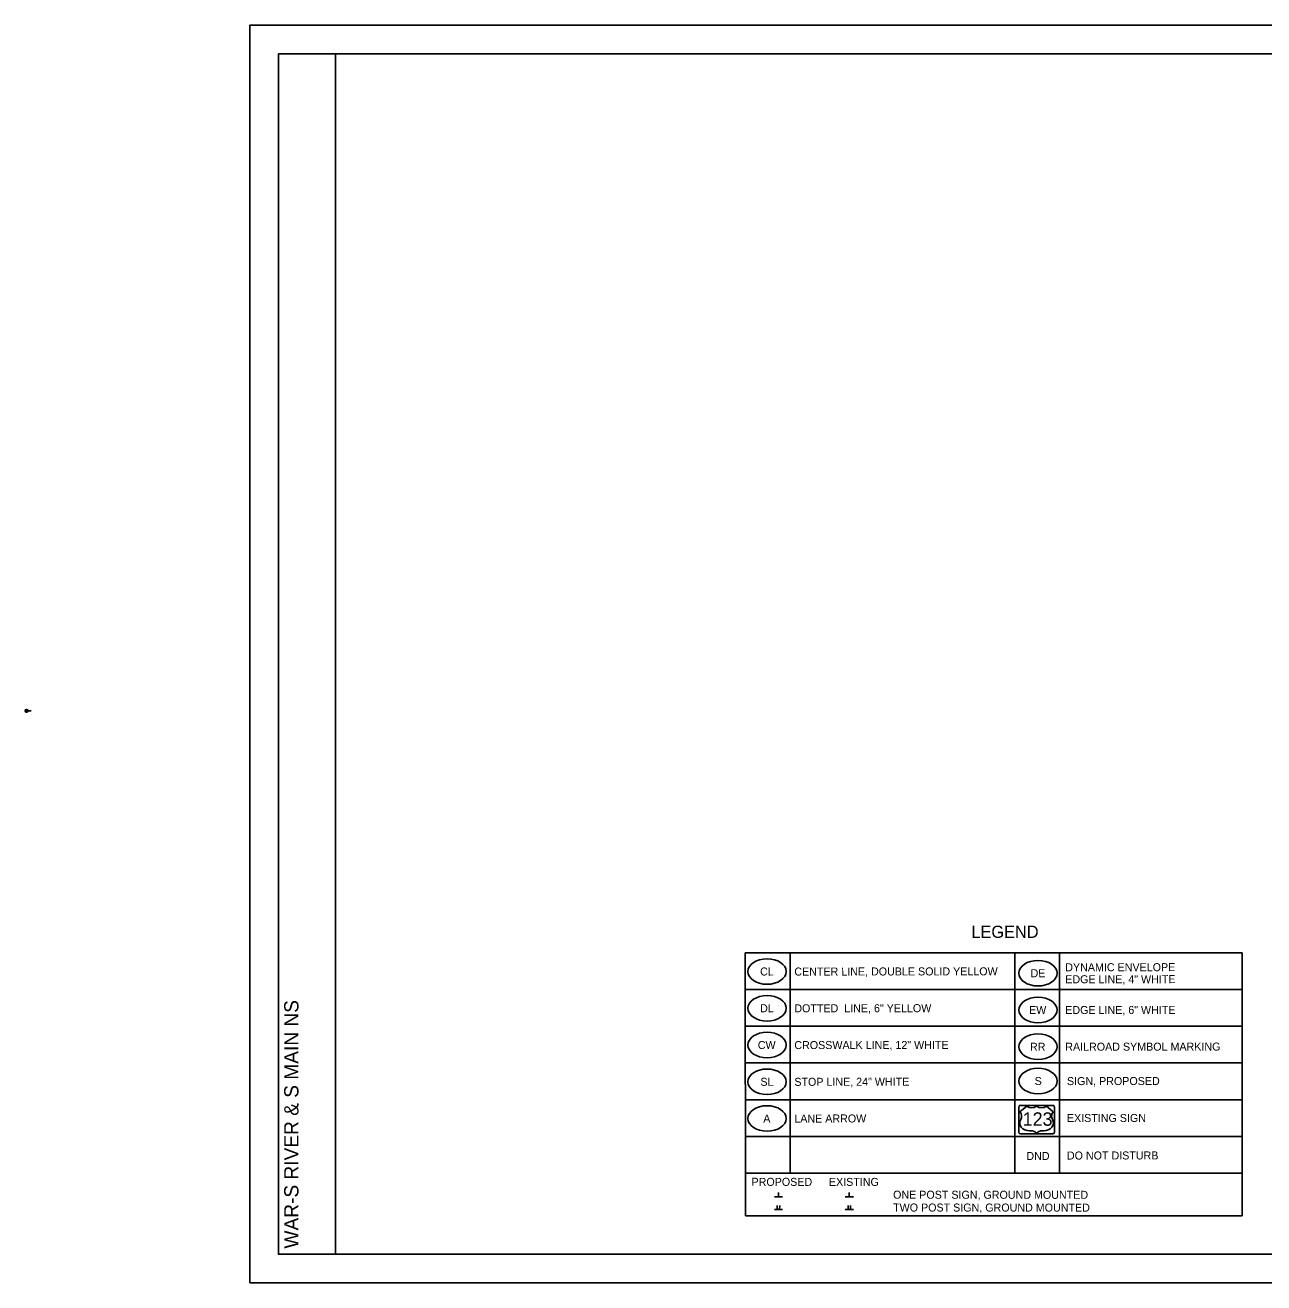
# Model space of a CAD drawing. Extents: x -3.9 to 34, y 0 to 22.
# Drawn here: x -3.93 to 17.74, y 0 to 22 of the extents above; entities that cross this region are included whole.
import ezdxf

# ---------------------------------------------------------------- set-up
doc = ezdxf.new("R2010")
doc.units = 0
for name, color, linetype in [('Default', 7, 'Continuous'), ('PM_P_CL_Double_Solid', 7, 'Continuous'), ('PM_P_Crosswalk', 7, 'Continuous'), ('PM_P_Edge_Line', 7, 'Continuous'), ('SN_P_Signs', 7, 'Continuous')]:
    doc.layers.add(name, color=color, linetype=linetype)

msp = doc.modelspace()

# ---------------------------------------------------------------- linework, layer by layer
at = {"layer": 'Default'}
for p, q in [((-3.932, 10.006), (-3.88, 10.006)), ((-3.906, 10.006), (-3.826, 10.006))]:
    msp.add_line(p, q, dxfattribs=at)
msp.add_circle((-3.906, 10.006), 0.026, dxfattribs=at)
at = {"layer": 'PM_P_CL_Double_Solid'}
msp.add_lwpolyline([(0, 0), (34, 0), (34, 22), (0, 22)], close=True, dxfattribs=at)
at = {"layer": 'PM_P_Crosswalk'}
for p, q in [((8.667, 5.774), (8.67, 1.174)), ((8.667, 5.774), (17.359, 5.774)), ((9.452, 5.774), (9.452, 1.917)), ((13.38, 5.774), (13.38, 1.917)), ((14.165, 5.774), (14.165, 1.917)), ((17.359, 5.774), (17.359, 1.174)), ((8.667, 5.131), (17.359, 5.131)), ((8.668, 4.488), (17.359, 4.488)), ((8.669, 3.846), (17.359, 3.846)), ((8.67, 3.203), (17.36, 3.203)), ((8.67, 2.56), (17.36, 2.56)), ((8.67, 1.917), (17.36, 1.917)), ((8.67, 1.174), (17.359, 1.174)), ((0.6, 0.6), (0.6, 0.6))]:
    msp.add_line(p, q, dxfattribs=at)
at = {"layer": 'PM_P_Edge_Line'}
for points in [[(0.5, 21.5), (1.5, 21.5), (1.5, 0.5), (0.5, 0.5)], [(1.5, 21.5), (33.5, 21.5), (33.5, 0.5), (1.5, 0.5)]]:
    msp.add_lwpolyline(points, close=True, dxfattribs=at)
at = {"layer": 'SN_P_Signs'}
for p, q in [((13.593, 3.09), (13.471, 2.992)), ((14.056, 2.992), (13.934, 3.09)), ((13.641, 2.66), (13.666, 2.66)), ((13.861, 2.66), (13.886, 2.66)), ((9.247, 1.507), (9.247, 1.579)), ((10.487, 1.506), (10.487, 1.578)), ((9.319, 1.507), (9.176, 1.507)), ((9.226, 1.284), (9.226, 1.355)), ((9.268, 1.284), (9.269, 1.355)), ((10.558, 1.506), (10.415, 1.506)), ((10.465, 1.283), (10.465, 1.355)), ((10.508, 1.283), (10.508, 1.355)), ((9.318, 1.284), (9.176, 1.284)), ((9.247, 1.284), (9.247, 1.284)), ((10.558, 1.283), (10.415, 1.283)), ((10.487, 1.283), (10.487, 1.283))]:
    msp.add_line(p, q, dxfattribs=at)
for points in [[(14.045, 3.105), (13.482, 3.105)], [(13.451, 3.074), (13.451, 2.637)], [(14.076, 2.637), (14.076, 3.074)], [(13.482, 2.605), (14.045, 2.605)]]:
    msp.add_lwpolyline(points, dxfattribs=at)
for centre, start, end in [((13.482, 3.074), 90, 180), ((14.045, 3.074), 360, 90), ((13.482, 2.637), 180, 270), ((14.045, 2.637), 270, 360)]:
    msp.add_arc(centre, 0.0313, start, end, dxfattribs=at)
for centre in [(9.048, 5.446), (13.788, 5.416), (9.048, 4.803), (13.788, 4.773), (9.048, 4.16), (13.788, 4.131), (9.048, 3.517), (13.789, 3.53), (9.048, 2.875)]:
    msp.add_ellipse(centre, major_axis=(0.335, 0), ratio=0.666667, dxfattribs=at)
for centre, major_axis, start_param, end_param in [((13.678, 3.159), (-0.122, 0), 0.795399, 2.346194), ((13.849, 3.159), (-0.122, 0), 0.795399, 2.346194), ((13.331, 2.914), (0.171, 0), 5.838949, 6.894067), ((14.196, 2.914), (-0.171, 0), 5.672304, 6.727422), ((13.64, 2.797), (0.171, 0), 2.702327, 4.723529), ((13.666, 2.562), (-0.122, 0), 3.785094, 4.712389), ((13.861, 2.562), (-0.122, 0), 4.712389, 5.639684), ((13.887, 2.797), (-0.171, 0), 1.559657, 3.580859)]:
    msp.add_ellipse(centre, major_axis=major_axis, ratio=0.8, start_param=start_param, end_param=end_param, dxfattribs=at)

# ---------------------------------------------------------------- texts
at = {"layer": 'Default'}
for s, p in [('P.16', (-3.91, 9.996)), ('1', (-3.907, 10.012)), ('Unnamed Plan - Plan 1', (-3.873, 10.012)), ('1:20', (-3.873, 9.996))]:
    msp.add_text(s, height=0.00328, dxfattribs=at).set_placement(p)
at = {"layer": 'PM_P_Crosswalk'}
msp.add_text('WAR-S RIVER & S MAIN NS', height=0.25, rotation=90, dxfattribs=at).set_placement((0.85, 0.6))
at = {"layer": 'SN_P_Signs'}
for s, height, rotation, p in [('LEGEND', 0.214, 0.0655, (12.622, 6.033)), ('CL', 0.14, 0.0655, (8.926, 5.376)), ('CENTER LINE, DOUBLE SOLID YELLOW', 0.14, 0.0655, (9.525, 5.375)), ('DYNAMIC ENVELOPE', 0.14, 0.0655, (14.265, 5.45)), ('DE', 0.14, 0.0655, (13.658, 5.346)), ('EDGE LINE, 4" WHITE', 0.14, 0.0655, (14.265, 5.24)), ('DL', 0.14, 0.0655, (8.926, 4.733)), ('DOTTED  LINE, 6" YELLOW', 0.14, 0.0655, (9.525, 4.732)), ('EW', 0.14, 0.0655, (13.632, 4.703)), ('EDGE LINE, 6" WHITE', 0.14, 0.0655, (14.265, 4.702)), ('CW', 0.14, 0.0655, (8.886, 4.09)), ('CROSSWALK LINE, 12" WHITE', 0.14, 0.0655, (9.525, 4.089)), ('RR', 0.14, 0.0655, (13.648, 4.06)), ('RAILROAD SYMBOL MARKING', 0.14, 0.0655, (14.265, 4.06)), ('SL', 0.14, 0.0655, (8.932, 3.447)), ('STOP LINE, 24" WHITE', 0.14, 0.0655, (9.525, 3.446)), ('S', 0.14, 0.0655, (13.729, 3.46)), ('SIGN, PROPOSED', 0.14, 0.0655, (14.295, 3.459)), ('A', 0.14, 0.0655, (8.982, 2.804)), ('LANE ARROW', 0.14, 0.0655, (9.525, 2.804)), ('123', 0.2344, 360, (13.52, 2.748)), ('EXISTING SIGN', 0.14, 0.0655, (14.294, 2.813)), ('DND', 0.14, 0.0655, (13.585, 2.149)), ('DO NOT DISTURB', 0.14, 0.0655, (14.294, 2.157)), ('PROPOSED', 0.14, 359.9605, (8.776, 1.697)), ('EXISTING', 0.14, 359.9605, (10.13, 1.696)), ('ONE POST SIGN, GROUND MOUNTED', 0.14, 359.9605, (11.253, 1.472)), ('TWO POST SIGN, GROUND MOUNTED', 0.14, 359.9605, (11.253, 1.248))]:
    msp.add_text(s, height=height, rotation=rotation, dxfattribs=at).set_placement(p)

doc.saveas('drawing.dxf')
